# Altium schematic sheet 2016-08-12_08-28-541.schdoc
size 334 x 177 mm; SheetNumber: 1; SheetTotal: 1
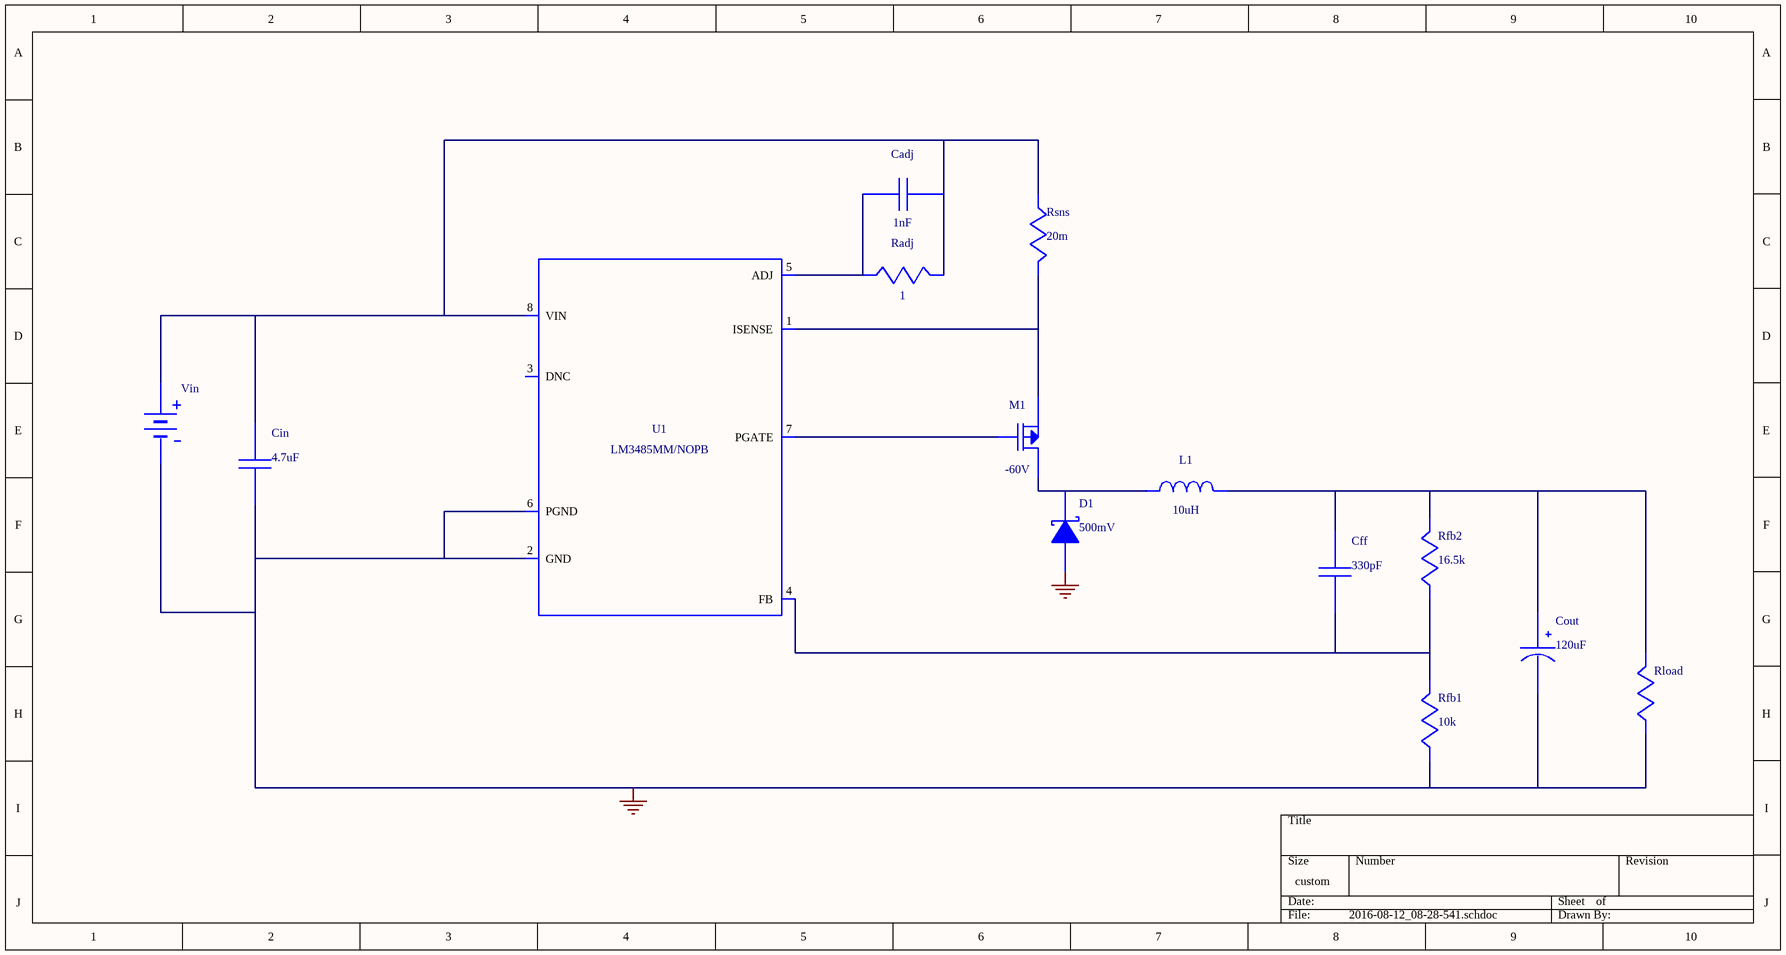
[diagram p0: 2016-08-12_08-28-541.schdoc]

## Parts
Cadj  value 1nF  (hidden comment: CL21C102JBCNFNC)
Cff  value 330pF  (hidden comment: CL21C331JBANFNC)
Cin  value 4.7uF  (hidden comment: GRM31CR71H475KA12L)
Cout  value 120uF  (hidden comment: GENERIC_CAP_POLARIZED)
D1  value 500mV  (hidden comment: B340A-13-F)
L1  value 10uH  (hidden comment: SRU1038-100Y)
M1  value -60V  (hidden comment: FDC5614P)
Radj  value 1  (hidden comment: CRCW04021R00FKED)
Rfb1  value 10k  (hidden comment: CRCW040210K0FKED)
Rfb2  value 16.5k  (hidden comment: CRCW040216K5FKED)
Rload  WB_LOAD_RESISTOR  (value not drawn)
Rsns  value 20m  (hidden comment: CSR1206FK20L0)
U1  LM3485MM/NOPB
Vin  WB_BATTERY  (value not drawn)

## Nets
0: Cin.2 Cout.2(-) D1.2(A) Rfb1.2 Rload.2 U1.2(GND) U1.6(PGND) Vin.2(-)
NetCadj_1: Cadj.1 Cin.1 Radj.1 Rsns.2 U1.8(VIN) Vin.1(+)
NetCadj_2: Cadj.2 Radj.2 U1.5(ADJ)
NetCff_1: Cff.1 Cout.1(+) L1.2 Rfb2.1 Rload.1
NetCff_2: Cff.2 Rfb1.1 Rfb2.2 U1.4(FB)
NetD1_1: D1.1(K) L1.1 M1.1(Drain) M1.2(Drain) M1.5(Drain) M1.6(Drain)
NetM1_3: M1.3(Gate) U1.7(PGATE)
NetM1_4: M1.4(Source) Rsns.1 U1.1(ISENSE)

Not connected (* = marked no-connect by the designer): U1 3(DNC)

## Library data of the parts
Cadj = CL21C102JBCNFNC: Manufacturer Name: Samsung Electro-Mechanics
Cff = CL21C331JBANFNC: Manufacturer Name: Samsung Electro-Mechanics
Cin = GRM31CR71H475KA12L: GRM31CR71H475KA1; Manufacturer Name: MuRata
Cout = GENERIC_CAP_POLARIZED: 6SVPC120MV; Manufacturer Name: Panasonic
D1 = B340A-13-F: Manufacturer Name: Diodes Inc.
L1 = SRU1038-100Y: Manufacturer Name: Bourns
M1 = FDC5614P: Manufacturer Name: Fairchild Semiconductor
Radj = CRCW04021R00FKED: Manufacturer Name: Vishay-Dale
Rfb1 = CRCW040210K0FKED: Manufacturer Name: Vishay-Dale
Rfb2 = CRCW040216K5FKED: Manufacturer Name: Vishay-Dale
Rsns = CSR1206FK20L0: Manufacturer Name: Stackpole Electronics Inc
U1 = LM3485MM/NOPB: Manufacturer Name: Texas Instruments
